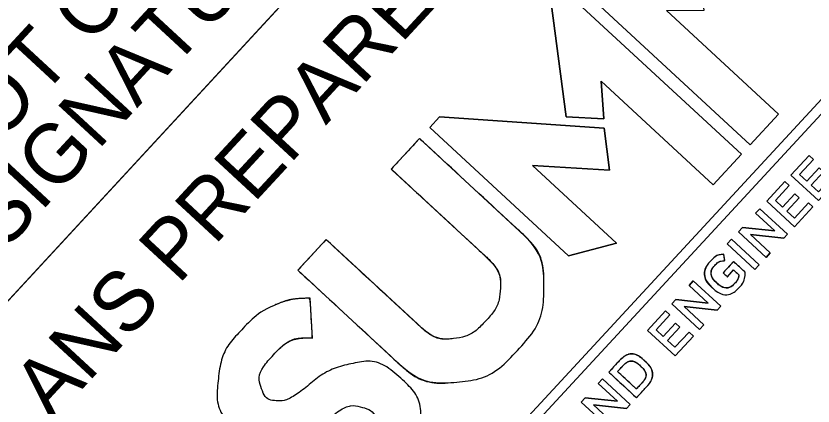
# Model space of a CAD drawing. Extents: x 1768064 to 1770025, y 999327 to 1001342.
# Drawn here: x 1769346.17 to 1769394.23, y 1001051.14 to 1001074.65 of the extents above; entities that cross this region are included whole.
import ezdxf

# ---------------------------------------------------------------- set-up
doc = ezdxf.new("R2010")
doc.units = 0
doc.layers.add('P_NCDOT_Horizontal_Alignment_Station_Major_Label', color=7, linetype='Continuous')

msp = doc.modelspace()

# ---------------------------------------------------------------- linework, layer by layer
at = {"layer": 'P_NCDOT_Horizontal_Alignment_Station_Major_Label'}
for p, q in [((1769393.035, 1001108.715), (1769325.198, 1001035.326)), ((1769388.904, 1001059.905), (1769388.847, 1001060.288)), ((1769388.153, 1001058.261), (1769388.157, 1001058.257)), ((1769388.425, 1001058.556), (1769388.42, 1001058.56)), ((1769364.05, 1001055.234), (1769363.905, 1001057.641)), ((1769384.083, 1001053.859), (1769384.078, 1001053.863)), ((1769383.811, 1001053.564), (1769383.815, 1001053.56))]:
    msp.add_line(p, q, dxfattribs=at)
msp.add_lwpolyline([(1769315.85, 1001043.967), (1769383.693, 1001117.362), (1769393.041, 1001108.721), (1769325.198, 1001035.326)], close=True, dxfattribs=at)
for points in [[(1769409.949, 1001085.219), (1769368.674, 1001040.566), (1769368.23, 1001040.976), (1769409.506, 1001085.629), (1769409.949, 1001085.219)], [(1769409.506, 1001085.629), (1769368.23, 1001040.976), (1769368.674, 1001040.566), (1769409.949, 1001085.219), (1769409.506, 1001085.629)], [(1769378.739, 1001077.704), (1769390.437, 1001066.891), (1769392.14, 1001068.734), (1769385.393, 1001074.971), (1769387.656, 1001074.995), (1769387.366, 1001077.253), (1769378.739, 1001077.704)], [(1769378.739, 1001077.704), (1769390.437, 1001066.891), (1769392.14, 1001068.734), (1769385.393, 1001074.971), (1769387.656, 1001074.995), (1769387.366, 1001077.253), (1769378.739, 1001077.704)], [(1769378.215, 1001077.137), (1769389.913, 1001066.324), (1769388.209, 1001064.481), (1769381.462, 1001070.718), (1769381.615, 1001068.46), (1769379.341, 1001068.572), (1769378.215, 1001077.137)], [(1769379.341, 1001068.572), (1769381.615, 1001068.46), (1769381.462, 1001070.718), (1769388.209, 1001064.481), (1769389.913, 1001066.324), (1769378.215, 1001077.137), (1769379.341, 1001068.572)], [(1769371.715, 1001068.578), (1769381.631, 1001067.89), (1769381.948, 1001065.359), (1769377.317, 1001065.638), (1769382.383, 1001060.956), (1769379.489, 1001060.186), (1769371.114, 1001067.928), (1769371.715, 1001068.578)], [(1769371.114, 1001067.928), (1769379.489, 1001060.186), (1769382.383, 1001060.956), (1769377.317, 1001065.638), (1769381.948, 1001065.359), (1769381.631, 1001067.89), (1769371.715, 1001068.578), (1769371.114, 1001067.928)], [(1769376.536, 1001061.689), (1769370.503, 1001067.266), (1769368.799, 1001065.423), (1769374.321, 1001060.319)], [(1769392.897, 1001065.064), (1769393.993, 1001066.25), (1769394.255, 1001066.007), (1769393.419, 1001065.103), (1769393.852, 1001064.702), (1769394.593, 1001065.504), (1769394.855, 1001065.262), (1769394.114, 1001064.46), (1769394.562, 1001064.046), (1769395.409, 1001064.963), (1769395.671, 1001064.72), (1769394.564, 1001063.524), (1769392.897, 1001065.064)], [(1769394.564, 1001063.524), (1769395.671, 1001064.72), (1769395.409, 1001064.963), (1769394.562, 1001064.046), (1769394.114, 1001064.46), (1769394.855, 1001065.262), (1769394.593, 1001065.504), (1769393.852, 1001064.702), (1769393.419, 1001065.103), (1769394.255, 1001066.007), (1769393.993, 1001066.25), (1769392.897, 1001065.064), (1769394.564, 1001063.524)], [(1769391.439, 1001063.489), (1769392.535, 1001064.675), (1769392.797, 1001064.433), (1769391.961, 1001063.528), (1769392.395, 1001063.127), (1769393.136, 1001063.929), (1769393.398, 1001063.687), (1769392.656, 1001062.885), (1769393.104, 1001062.472), (1769393.951, 1001063.388), (1769394.213, 1001063.145), (1769393.106, 1001061.948), (1769391.439, 1001063.489)], [(1769393.106, 1001061.948), (1769394.213, 1001063.145), (1769393.951, 1001063.388), (1769393.104, 1001062.472), (1769392.656, 1001062.885), (1769393.398, 1001063.687), (1769393.136, 1001063.929), (1769392.395, 1001063.127), (1769391.961, 1001063.528), (1769392.797, 1001064.433), (1769392.535, 1001064.675), (1769391.439, 1001063.489), (1769393.106, 1001061.948)], [(1769389.73, 1001061.64), (1769389.971, 1001061.9), (1769391.915, 1001061.691), (1769390.762, 1001062.757), (1769391.018, 1001063.033), (1769392.685, 1001061.492), (1769392.467, 1001061.257), (1769390.466, 1001061.472), (1769391.652, 1001060.375), (1769391.397, 1001060.099), (1769389.73, 1001061.64)], [(1769391.397, 1001060.099), (1769391.652, 1001060.375), (1769390.466, 1001061.472), (1769392.467, 1001061.257), (1769392.685, 1001061.492), (1769391.018, 1001063.033), (1769390.762, 1001062.757), (1769391.915, 1001061.691), (1769389.971, 1001061.9), (1769389.73, 1001061.64), (1769391.397, 1001060.099)], [(1769370.39, 1001056.067), (1769364.868, 1001061.171), (1769363.165, 1001059.328), (1769369.199, 1001053.751)], [(1769389.054, 1001060.909), (1769389.314, 1001061.19), (1769390.981, 1001059.649), (1769390.721, 1001059.368), (1769389.054, 1001060.909)], [(1769390.721, 1001059.368), (1769390.981, 1001059.649), (1769389.314, 1001061.19), (1769389.054, 1001060.909), (1769390.721, 1001059.368)], [(1769390.138, 1001059.2), (1769389.438, 1001059.848), (1769388.809, 1001059.167), (1769389.063, 1001058.931), (1769389.441, 1001059.34), (1769389.753, 1001059.052)], [(1769385.717, 1001057.298), (1769385.958, 1001057.559), (1769387.902, 1001057.35), (1769386.749, 1001058.415), (1769387.005, 1001058.692), (1769388.672, 1001057.151), (1769388.454, 1001056.916), (1769386.453, 1001057.13), (1769387.639, 1001056.034), (1769387.384, 1001055.758), (1769385.717, 1001057.298)], [(1769387.384, 1001055.758), (1769387.639, 1001056.034), (1769386.453, 1001057.13), (1769388.454, 1001056.916), (1769388.672, 1001057.151), (1769387.005, 1001058.692), (1769386.749, 1001058.415), (1769387.902, 1001057.35), (1769385.958, 1001057.559), (1769385.717, 1001057.298), (1769387.384, 1001055.758)], [(1769384.24, 1001055.7), (1769385.335, 1001056.885), (1769385.597, 1001056.643), (1769384.761, 1001055.739), (1769385.194, 1001055.338), (1769385.935, 1001056.14), (1769386.197, 1001055.898), (1769385.456, 1001055.096), (1769385.904, 1001054.682), (1769386.751, 1001055.598), (1769387.013, 1001055.356), (1769385.906, 1001054.159), (1769384.24, 1001055.7)], [(1769385.906, 1001054.159), (1769387.013, 1001055.356), (1769386.751, 1001055.598), (1769385.904, 1001054.682), (1769385.456, 1001055.096), (1769386.197, 1001055.898), (1769385.935, 1001056.14), (1769385.194, 1001055.338), (1769384.761, 1001055.739), (1769385.597, 1001056.643), (1769385.335, 1001056.885), (1769384.24, 1001055.7), (1769385.906, 1001054.159)], [(1769382.464, 1001053.78), (1769381.913, 1001053.183), (1769383.58, 1001051.643), (1769384.131, 1001052.239)], [(1769383.865, 1001052.485), (1769383.573, 1001052.17), (1769382.44, 1001053.218), (1769382.731, 1001053.533)], [(1769380.246, 1001051.379), (1769380.486, 1001051.64), (1769382.43, 1001051.431), (1769381.278, 1001052.496), (1769381.534, 1001052.773), (1769383.201, 1001051.232), (1769382.983, 1001050.997), (1769380.982, 1001051.211), (1769382.168, 1001050.115), (1769381.913, 1001049.838), (1769380.246, 1001051.379)], [(1769381.913, 1001049.838), (1769382.168, 1001050.115), (1769380.982, 1001051.211), (1769382.983, 1001050.997), (1769383.201, 1001051.232), (1769381.534, 1001052.773), (1769381.278, 1001052.496), (1769382.43, 1001051.431), (1769380.486, 1001051.64), (1769380.246, 1001051.379), (1769381.913, 1001049.838)]]:
    msp.add_lwpolyline(points, dxfattribs=at)
for points, degree in [([(1769364.868, 1001061.171), (1769364.868, 1001061.171), (1769370.39, 1001056.067), (1769370.39, 1001056.067), (1769371.115, 1001055.396), (1769371.841, 1001055.113), (1769372.559, 1001055.206), (1769373.279, 1001055.3), (1769373.923, 1001055.656), (1769374.49, 1001056.269), (1769375.057, 1001056.882), (1769375.338, 1001057.528), (1769375.374, 1001058.252), (1769375.411, 1001058.976), (1769375.046, 1001059.649), (1769374.321, 1001060.319), (1769374.321, 1001060.319), (1769368.799, 1001065.423), (1769368.799, 1001065.423), (1769368.799, 1001065.423), (1769370.503, 1001067.266), (1769370.503, 1001067.266), (1769370.503, 1001067.266), (1769376.536, 1001061.689), (1769376.536, 1001061.689), (1769377.517, 1001060.783), (1769378.019, 1001059.659), (1769378.001, 1001058.272), (1769377.984, 1001056.886), (1769377.458, 1001055.632), (1769376.4, 1001054.488), (1769375.342, 1001053.343), (1769374.121, 1001052.707), (1769372.741, 1001052.581), (1769371.359, 1001052.455), (1769370.179, 1001052.844), (1769369.199, 1001053.751), (1769369.199, 1001053.751), (1769363.165, 1001059.328), (1769363.165, 1001059.328), (1769363.165, 1001059.328), (1769364.868, 1001061.171), (1769364.868, 1001061.171)], 3), ([(1769369.199, 1001053.751), (1769370.179, 1001052.844), (1769371.359, 1001052.455), (1769372.741, 1001052.581), (1769374.121, 1001052.707), (1769375.342, 1001053.343), (1769376.4, 1001054.488), (1769377.458, 1001055.632), (1769377.984, 1001056.886), (1769378.001, 1001058.272), (1769378.019, 1001059.659), (1769377.517, 1001060.783), (1769376.536, 1001061.689)], 3), ([(1769374.321, 1001060.319), (1769375.046, 1001059.649), (1769375.411, 1001058.976), (1769375.374, 1001058.252), (1769375.338, 1001057.528), (1769375.057, 1001056.882), (1769374.49, 1001056.269), (1769373.923, 1001055.656), (1769373.279, 1001055.3), (1769372.559, 1001055.206), (1769371.841, 1001055.113), (1769371.115, 1001055.396), (1769370.39, 1001056.067)], 3), ([(1769388.157, 1001058.257), (1769388.157, 1001058.257), (1769388.153, 1001058.261), (1769388.153, 1001058.261), (1769387.686, 1001058.693), (1769387.607, 1001059.401), (1769388.053, 1001059.883), (1769388.31, 1001060.161), (1769388.55, 1001060.258), (1769388.847, 1001060.288), (1769388.847, 1001060.288), (1769388.904, 1001059.905), (1769388.904, 1001059.905), (1769388.68, 1001059.883), (1769388.499, 1001059.826), (1769388.311, 1001059.623), (1769388.039, 1001059.328), (1769388.101, 1001058.855), (1769388.42, 1001058.56), (1769388.42, 1001058.56), (1769388.425, 1001058.556), (1769388.425, 1001058.556), (1769388.768, 1001058.239), (1769389.221, 1001058.223), (1769389.523, 1001058.549), (1769389.662, 1001058.7), (1769389.739, 1001058.883), (1769389.753, 1001059.052), (1769389.753, 1001059.052), (1769389.441, 1001059.34), (1769389.441, 1001059.34), (1769389.441, 1001059.34), (1769389.063, 1001058.931), (1769389.063, 1001058.931), (1769389.063, 1001058.931), (1769388.809, 1001059.167), (1769388.809, 1001059.167), (1769388.809, 1001059.167), (1769389.438, 1001059.848), (1769389.438, 1001059.848), (1769389.438, 1001059.848), (1769390.138, 1001059.2), (1769390.138, 1001059.2), (1769390.133, 1001058.913), (1769390.043, 1001058.577), (1769389.781, 1001058.294), (1769389.319, 1001057.793), (1769388.643, 1001057.808), (1769388.157, 1001058.257)], 3), ([(1769388.847, 1001060.288), (1769388.55, 1001060.258), (1769388.31, 1001060.161), (1769388.053, 1001059.883), (1769387.607, 1001059.401), (1769387.686, 1001058.693), (1769388.153, 1001058.261)], 3), ([(1769388.42, 1001058.56), (1769388.101, 1001058.855), (1769388.039, 1001059.328), (1769388.311, 1001059.623), (1769388.499, 1001059.826), (1769388.68, 1001059.883), (1769388.904, 1001059.905)], 3), ([(1769388.157, 1001058.257), (1769388.643, 1001057.808), (1769389.319, 1001057.793), (1769389.781, 1001058.294), (1769390.043, 1001058.577), (1769390.133, 1001058.913), (1769390.138, 1001059.2)], 3), ([(1769389.753, 1001059.052), (1769389.739, 1001058.883), (1769389.662, 1001058.7), (1769389.523, 1001058.549), (1769389.221, 1001058.223), (1769388.768, 1001058.239), (1769388.425, 1001058.556)], 3), ([(1769361.728, 1001057.209), (1769362.375, 1001057.483), (1769363.101, 1001057.627), (1769363.905, 1001057.641), (1769363.905, 1001057.641), (1769364.05, 1001055.234), (1769364.05, 1001055.234), (1769363.161, 1001055.297), (1769362.376, 1001054.962), (1769361.696, 1001054.226), (1769361.016, 1001053.49), (1769360.763, 1001052.853), (1769360.936, 1001052.313), (1769361.11, 1001051.774), (1769361.418, 1001051.489), (1769361.863, 1001051.457), (1769362.308, 1001051.425), (1769362.934, 1001051.718), (1769363.741, 1001052.335), (1769364.544, 1001053.033), (1769365.463, 1001053.492), (1769366.496, 1001053.712), (1769367.529, 1001053.932), (1769368.535, 1001053.589), (1769369.515, 1001052.682), (1769370.283, 1001051.973), (1769370.631, 1001051.025), (1769370.559, 1001049.837), (1769370.488, 1001048.648), (1769370.037, 1001047.604), (1769369.205, 1001046.704), (1769368.416, 1001045.85), (1769367.629, 1001045.255), (1769366.844, 1001044.919), (1769366.059, 1001044.584), (1769365.265, 1001044.409), (1769364.462, 1001044.394), (1769364.462, 1001044.394), (1769364.317, 1001046.802), (1769364.317, 1001046.802), (1769365.206, 1001046.738), (1769366.146, 1001047.157), (1769367.138, 1001048.059), (1769367.894, 1001048.877), (1769368.184, 1001049.554), (1769368.009, 1001050.091), (1769367.834, 1001050.628), (1769367.471, 1001050.963), (1769366.922, 1001051.096), (1769366.373, 1001051.228), (1769365.678, 1001050.924), (1769364.837, 1001050.186), (1769364.072, 1001049.529), (1769363.214, 1001049.071), (1769362.263, 1001048.813), (1769361.313, 1001048.554), (1769360.369, 1001048.858), (1769359.432, 1001049.724), (1769358.584, 1001050.508), (1769358.226, 1001051.486), (1769358.356, 1001052.658), (1769358.486, 1001053.83), (1769358.892, 1001054.783), (1769359.572, 1001055.518), (1769360.362, 1001056.373), (1769361.08, 1001056.937), (1769361.728, 1001057.209)], 3), ([(1769361.728, 1001057.209), (1769361.08, 1001056.937), (1769360.362, 1001056.373), (1769359.572, 1001055.518), (1769358.892, 1001054.783), (1769358.486, 1001053.83), (1769358.356, 1001052.658), (1769358.226, 1001051.486), (1769358.584, 1001050.508), (1769359.432, 1001049.724), (1769360.369, 1001048.858), (1769361.313, 1001048.554), (1769362.263, 1001048.813), (1769363.214, 1001049.071), (1769364.072, 1001049.529), (1769364.837, 1001050.186), (1769365.678, 1001050.924), (1769366.373, 1001051.228), (1769366.922, 1001051.096), (1769367.471, 1001050.963), (1769367.834, 1001050.628), (1769368.009, 1001050.091), (1769368.184, 1001049.554), (1769367.894, 1001048.877), (1769367.138, 1001048.059), (1769366.146, 1001047.157), (1769365.206, 1001046.738), (1769364.317, 1001046.802)], 3), ([(1769363.905, 1001057.641), (1769363.101, 1001057.627), (1769362.375, 1001057.483), (1769361.728, 1001057.209)], 2), ([(1769364.462, 1001044.394), (1769365.265, 1001044.409), (1769366.059, 1001044.584), (1769366.844, 1001044.919), (1769367.629, 1001045.255), (1769368.416, 1001045.85), (1769369.205, 1001046.704), (1769370.037, 1001047.604), (1769370.488, 1001048.648), (1769370.559, 1001049.837), (1769370.631, 1001051.025), (1769370.283, 1001051.973), (1769369.515, 1001052.682), (1769368.535, 1001053.589), (1769367.529, 1001053.932), (1769366.496, 1001053.712), (1769365.463, 1001053.492), (1769364.544, 1001053.033), (1769363.741, 1001052.335), (1769362.934, 1001051.718), (1769362.308, 1001051.425), (1769361.863, 1001051.457), (1769361.418, 1001051.489), (1769361.11, 1001051.774), (1769360.936, 1001052.313), (1769360.763, 1001052.853), (1769361.016, 1001053.49), (1769361.696, 1001054.226), (1769362.376, 1001054.962), (1769363.161, 1001055.297), (1769364.05, 1001055.234)], 3), ([(1769381.913, 1001053.183), (1769381.913, 1001053.183), (1769382.464, 1001053.78), (1769382.464, 1001053.78), (1769382.929, 1001054.282), (1769383.609, 1001054.297), (1769384.078, 1001053.863), (1769384.078, 1001053.863), (1769384.083, 1001053.859), (1769384.083, 1001053.859), (1769384.552, 1001053.425), (1769384.596, 1001052.741), (1769384.131, 1001052.239), (1769384.131, 1001052.239), (1769383.58, 1001051.643), (1769383.58, 1001051.643), (1769383.58, 1001051.643), (1769381.913, 1001053.183), (1769381.913, 1001053.183)], 3), ([(1769382.44, 1001053.218), (1769382.44, 1001053.218), (1769383.573, 1001052.17), (1769383.573, 1001052.17), (1769383.573, 1001052.17), (1769383.865, 1001052.485), (1769383.865, 1001052.485), (1769384.175, 1001052.821), (1769384.142, 1001053.258), (1769383.815, 1001053.56), (1769383.815, 1001053.56), (1769383.811, 1001053.564), (1769383.811, 1001053.564), (1769383.484, 1001053.866), (1769383.041, 1001053.869), (1769382.731, 1001053.533), (1769382.731, 1001053.533), (1769382.44, 1001053.218), (1769382.44, 1001053.218)], 3), ([(1769384.078, 1001053.863), (1769383.609, 1001054.297), (1769382.929, 1001054.282), (1769382.464, 1001053.78)], 2), ([(1769382.731, 1001053.533), (1769383.041, 1001053.869), (1769383.484, 1001053.866), (1769383.811, 1001053.564)], 2), ([(1769384.131, 1001052.239), (1769384.596, 1001052.741), (1769384.552, 1001053.425), (1769384.083, 1001053.859)], 2), ([(1769383.815, 1001053.56), (1769384.142, 1001053.258), (1769384.175, 1001052.821), (1769383.865, 1001052.485)], 2)]:
    msp.add_open_spline(points, degree=degree, dxfattribs=at)

# ---------------------------------------------------------------- texts
for s, height, p in [('DOCUMENT NOT CONSIDERED FINAL', 3.59815, (1769323.012, 1001042.99)), ('UNLESS ALL SIGNATURES COMPLETED', 3.59815, (1769324.782, 1001038.045)), ('PLANS PREPARED BY:', 3.59788, (1769344.337, 1001045.843)), ('NC FIRM LICENSE No: C-5176', 4.55564, (1769361.678, 1001008.716)), ('1000 Social St. Suite 800.', 4.55564, (1769372.975, 1001009.653)), ('Raleigh, NC 27609', 4.55564, (1769383.831, 1001012.68))]:
    msp.add_text(s, height=height, rotation=47.2512, dxfattribs=at).set_placement(p)

doc.saveas('drawing.dxf')
